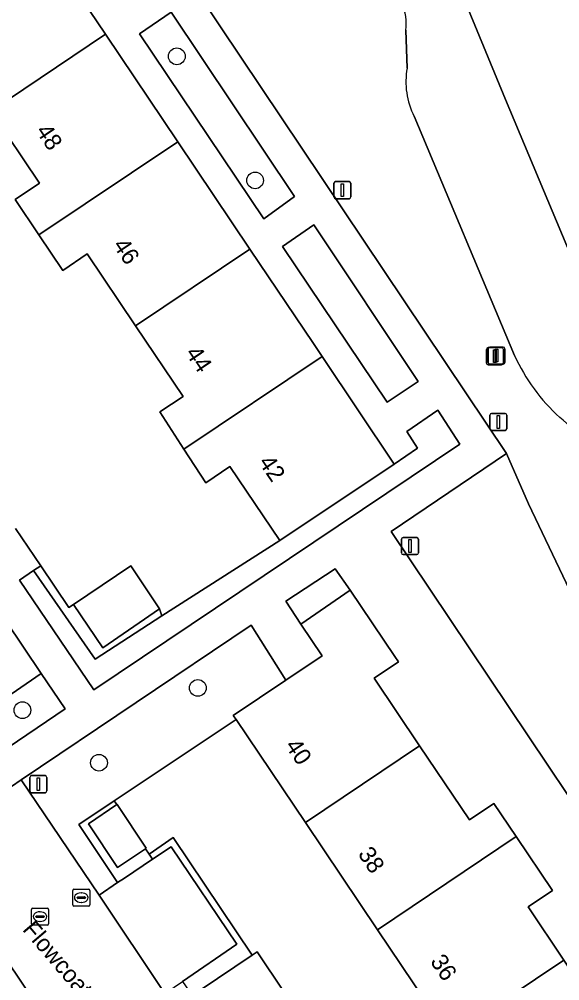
# Model space of a CAD drawing. Extents: x 158793 to 159888, y 384317 to 385256.
# Drawn here: x 159223.3 to 159254.9, y 384648 to 384704.4 of the extents above; entities that cross this region are included whole.
import ezdxf

# ---------------------------------------------------------------- set-up
doc = ezdxf.new("R2010")
doc.units = 0
for name, color, linetype in [('IMGEO_Berm_groen', 7, 'Continuous'), ('IMGEO_Boom', 7, 'Continuous'), ('IMGEO_Erf', 7, 'Continuous'), ('IMGEO_Groenvoorziening', 7, 'Continuous'), ('IMGEO_Kolk', 7, 'Continuous'), ('IMGEO_Lichtmast', 7, 'Continuous'), ('IMGEO_Openbare_ruimte_label', 7, 'Continuous'), ('IMGEO_Pand', 7, 'Continuous'), ('IMGEO_Pand_nummerreeks', 7, 'Continuous'), ('IMGEO_Parkeervlak_open', 7, 'Continuous'), ('IMGEO_Rijbaan_lokaal_gesloten', 7, 'Continuous'), ('IMGEO_Rijbaan_lokaal_open', 7, 'Continuous'), ('IMGEO_Rioolput', 7, 'Continuous'), ('IMGEO_Voetpad_open', 7, 'Continuous')]:
    doc.layers.add(name, color=color, linetype=linetype)

msp = doc.modelspace()

# ---------------------------------------------------------------- linework, layer by layer
at = {"layer": 'IMGEO_Berm_groen'}
msp.add_lwpolyline([(159216.952, 384783.693), (159217.253, 384782.828), (159218.327, 384780.517), (159221.58, 384772.678), (159236.092, 384737.711), (159251.77, 384699.675), (159258.087, 384684.588), (159260.49, 384679.327)], dxfattribs=at)
at = {"layer": 'IMGEO_Boom'}
for centre in [(159232.517, 384702.214), (159237.1, 384694.943), (159233.747, 384665.203), (159223.472, 384663.899), (159227.958, 384660.819)]:
    msp.add_circle(centre, 0.489, dxfattribs=at)
at = {"layer": 'IMGEO_Erf'}
for points in [[(159223.073, 384674.553), (159224.542, 384672.365), (159226.19, 384669.91), (159226.456, 384670.099), (159229.817, 384672.35), (159231.505, 384669.83), (159231.646, 384669.425), (159238.559, 384673.833), (159235.628, 384678.178), (159234.209, 384677.22), (159232.929, 384679.198), (159231.513, 384681.385), (159232.888, 384682.274), (159230.104, 384686.42), (159227.265, 384690.647), (159225.845, 384689.669), (159224.442, 384691.752), (159223.043, 384693.829), (159224.471, 384694.783), (159221.632, 384698.999)], [(159248.484, 384644.756), (159244.264, 384651.036), (159240.043, 384657.316), (159235.992, 384663.344), (159228.851, 384658.586), (159228.997, 384658.366), (159229.018, 384658.38), (159230.722, 384655.81), (159230.672, 384655.776), (159230.889, 384655.463), (159232.311, 384656.433), (159236.938, 384649.541), (159237.216, 384649.728), (159238.803, 384647.366)]]:
    msp.add_lwpolyline(points, dxfattribs=at)
at = {"layer": 'IMGEO_Groenvoorziening'}
for points in [[(159201.289, 384776.877), (159195.743, 384773.179), (159198.516, 384769.05), (159229.19, 384723.379), (159224.283, 384720.074), (159251.833, 384678.94), (159253.112, 384675.993), (159259.952, 384661.651), (159264.67, 384652.66), (159271.444, 384640.927), (159281.072, 384626.042), (159295.14, 384605.026), (159302.978, 384593.779), (159290.294, 384585.213), (159293.251, 384580.83)], [(159246.008, 384701.523), (159245.924, 384703.745)], [(159252.293, 384684.682), (159246.42, 384698.698)], [(159271.444, 384640.927), (159264.67, 384652.66), (159259.952, 384661.651), (159253.112, 384675.993), (159251.833, 384678.94), (159245.073, 384674.375), (159284.084, 384616.156)], [(159224.563, 384666.045), (159220.723, 384663.409)], [(159222.071, 384661.335), (159225.982, 384663.968), (159224.563, 384666.045)]]:
    msp.add_lwpolyline(points, dxfattribs=at)
for points in [[(159232.178, 384704.793), (159230.331, 384703.528), (159237.614, 384692.69), (159239.413, 384693.992)], [(159240.532, 384692.345), (159238.702, 384691.07), (159244.836, 384681.942), (159246.66, 384683.164)], [(159249.098, 384679.489), (159247.796, 384681.472), (159245.986, 384680.232), (159246.612, 384679.247), (159245.244, 384678.321), (159238.559, 384673.833), (159231.646, 384669.425), (159227.728, 384666.883), (159224.118, 384672.075), (159223.306, 384671.521), (159227.65, 384665.089)], [(159231.646, 384669.425), (159231.505, 384669.83), (159228.174, 384667.554), (159226.456, 384670.099), (159226.19, 384669.91), (159224.542, 384672.365), (159224.118, 384672.075), (159227.728, 384666.883)], [(159242.671, 384670.925), (159241.796, 384672.189), (159238.901, 384670.278), (159239.783, 384668.942)], [(159238.906, 384665.665), (159236.861, 384668.877), (159223.405, 384659.813), (159227.961, 384653.066), (159229.047, 384653.792), (159226.779, 384657.195), (159228.851, 384658.586), (159235.992, 384663.344), (159235.822, 384663.596)], [(159227.336, 384657.246), (159228.997, 384658.366), (159228.851, 384658.586), (159226.779, 384657.195), (159229.047, 384653.792), (159229.443, 384654.057), (159231.097, 384655.163), (159230.889, 384655.463), (159230.672, 384655.776), (159229.039, 384654.685)], [(159236.938, 384649.541), (159232.311, 384656.433), (159230.889, 384655.463), (159231.097, 384655.163), (159232.19, 384655.894), (159236.032, 384650.179), (159232.839, 384648.004), (159237.377, 384641.427), (159239.267, 384642.679), (159238.692, 384643.486), (159237.227, 384642.502), (159235.466, 384645.123), (159233.876, 384647.489)]]:
    msp.add_lwpolyline(points, close=True, dxfattribs=at)
for centre, radius, start, end in [((159242.978, 384704.132), 2.971, 352.5249, 23.1992), ((159250.334, 384700.711), 4.402, 169.374, 207.2212), ((159262.54, 384689.392), 11.277, 204.6838, 227.6579), ((159249.727, 384674.638), 8.271, 22.037, 50.8966)]:
    msp.add_arc(centre, radius, start, end, dxfattribs=at)
at = {"layer": 'IMGEO_Kolk'}
for p, q in [((159226.419, 384652.488), (159226.419, 384653.34)), ((159226.494, 384653.414), (159227.346, 384653.414)), ((159226.907, 384653.194), (159226.932, 384653.194)), ((159227.42, 384653.34), (159227.42, 384652.488)), ((159226.678, 384652.908), (159226.678, 384652.92)), ((159227.116, 384652.871), (159226.718, 384652.871)), ((159226.721, 384652.957), (159227.119, 384652.957)), ((159226.93, 384652.634), (159226.905, 384652.634)), ((159227.162, 384652.92), (159227.162, 384652.908)), ((159227.346, 384652.414), (159226.494, 384652.414))]:
    msp.add_line(p, q, dxfattribs=at)
for points in [[(159226.419, 384652.488), (159226.419, 384653.34)], [(159226.494, 384653.414), (159227.346, 384653.414)], [(159227.42, 384653.34), (159227.42, 384652.488)], [(159227.346, 384652.414), (159226.494, 384652.414)]]:
    msp.add_lwpolyline(points, dxfattribs=at)
for centre, radius, start, end in [((159226.496, 384653.338), 0.0765, 91.552, 178.448), ((159226.496, 384653.338), 0.0765, 91.552, 178.448), ((159227.344, 384653.338), 0.0765, 1.552, 88.448), ((159227.344, 384653.338), 0.0765, 1.552, 88.448), ((159226.718, 384652.917), 0.0403, 85.8775, 175.7526), ((159226.715, 384652.907), 0.0366, 178.938, 274.7102), ((159227.119, 384652.914), 0.043, 264.8664, 352.4533), ((159227.123, 384652.919), 0.0386, 1.7309, 96.639), ((159226.496, 384652.49), 0.0765, 181.552, 268.448), ((159226.496, 384652.49), 0.0765, 181.552, 268.448), ((159227.344, 384652.49), 0.0765, 271.552, 358.448), ((159227.344, 384652.49), 0.0765, 271.552, 358.448)]:
    msp.add_arc(centre, radius, start, end, dxfattribs=at)
for centre, major_axis, ratio, start_param, end_param in [((159226.906, 384652.914), (-0.387, 0.002), 0.722429, 4.712389, 7.853982), ((159226.931, 384652.914), (-0.39, 0.002), 0.717154, 1.570796, 4.712389)]:
    msp.add_ellipse(centre, major_axis=major_axis, ratio=ratio, start_param=start_param, end_param=end_param, dxfattribs=at)
at = {"layer": 'IMGEO_Lichtmast'}
for p, q in [((159241.815, 384694.873), (159242.605, 384694.873)), ((159242.605, 384694.873), (159241.815, 384694.873)), ((159241.715, 384693.973), (159241.715, 384694.773)), ((159241.715, 384694.773), (159241.715, 384693.973)), ((159242.705, 384694.773), (159242.705, 384693.973)), ((159242.705, 384693.973), (159242.705, 384694.773)), ((159242.605, 384693.873), (159241.815, 384693.873)), ((159241.815, 384693.873), (159242.605, 384693.873)), ((159250.65, 384684.242), (159250.65, 384685.042)), ((159250.65, 384685.042), (159250.65, 384684.242)), ((159250.745, 384684.279), (159250.745, 384685.079)), ((159250.745, 384685.079), (159250.745, 384684.279)), ((159250.75, 384685.142), (159251.54, 384685.142)), ((159251.54, 384685.142), (159250.75, 384685.142)), ((159250.845, 384685.179), (159251.635, 384685.179)), ((159251.635, 384685.179), (159250.845, 384685.179)), ((159251.64, 384685.042), (159251.64, 384684.242)), ((159251.64, 384684.242), (159251.64, 384685.042)), ((159251.735, 384685.079), (159251.735, 384684.279)), ((159251.735, 384684.279), (159251.735, 384685.079)), ((159251.54, 384684.142), (159250.75, 384684.142)), ((159250.75, 384684.142), (159251.54, 384684.142)), ((159251.635, 384684.179), (159250.845, 384684.179)), ((159250.845, 384684.179), (159251.635, 384684.179)), ((159250.952, 384681.288), (159251.742, 384681.288)), ((159251.742, 384681.288), (159250.952, 384681.288)), ((159250.852, 384680.388), (159250.852, 384681.188)), ((159250.852, 384681.188), (159250.852, 384680.388)), ((159251.842, 384681.188), (159251.842, 384680.388)), ((159251.842, 384680.388), (159251.842, 384681.188)), ((159251.742, 384680.288), (159250.952, 384680.288)), ((159250.952, 384680.288), (159251.742, 384680.288)), ((159245.775, 384674.016), (159246.565, 384674.016)), ((159246.565, 384674.016), (159245.775, 384674.016)), ((159245.675, 384673.116), (159245.675, 384673.916)), ((159245.675, 384673.916), (159245.675, 384673.116)), ((159246.665, 384673.916), (159246.665, 384673.116)), ((159246.665, 384673.116), (159246.665, 384673.916)), ((159246.565, 384673.016), (159245.775, 384673.016)), ((159245.775, 384673.016), (159246.565, 384673.016)), ((159223.913, 384659.163), (159223.913, 384659.963)), ((159223.913, 384659.963), (159223.913, 384659.163)), ((159224.013, 384660.063), (159224.803, 384660.063)), ((159224.803, 384660.063), (159224.013, 384660.063)), ((159224.903, 384659.963), (159224.903, 384659.163)), ((159224.903, 384659.163), (159224.903, 384659.963)), ((159224.803, 384659.063), (159224.013, 384659.063)), ((159224.013, 384659.063), (159224.803, 384659.063))]:
    msp.add_line(p, q, dxfattribs=at)
for points in [[(159242.135, 384694.748), (159242.285, 384694.748), (159242.285, 384693.998), (159242.135, 384693.998), (159242.135, 384694.748)], [(159251.07, 384685.017), (159251.22, 384685.017), (159251.22, 384684.267), (159251.07, 384684.267), (159251.07, 384685.017)], [(159251.165, 384685.054), (159251.315, 384685.054), (159251.315, 384684.304), (159251.165, 384684.304), (159251.165, 384685.054)], [(159251.272, 384681.163), (159251.422, 384681.163), (159251.422, 384680.413), (159251.272, 384680.413), (159251.272, 384681.163)], [(159246.095, 384673.891), (159246.245, 384673.891), (159246.245, 384673.141), (159246.095, 384673.141), (159246.095, 384673.891)], [(159224.333, 384659.938), (159224.483, 384659.938), (159224.483, 384659.188), (159224.333, 384659.188), (159224.333, 384659.938)]]:
    msp.add_lwpolyline(points, dxfattribs=at)
for centre, start, end in [((159241.815, 384694.773), 90, 180), ((159241.815, 384694.773), 90, 180), ((159242.605, 384694.773), 0, 90), ((159242.605, 384694.773), 360, 90), ((159241.815, 384693.973), 180, 270), ((159241.815, 384693.973), 180, 270), ((159242.605, 384693.973), 270, 0), ((159242.605, 384693.973), 270, 0), ((159250.75, 384685.042), 90, 180), ((159250.75, 384685.042), 90, 180), ((159250.845, 384685.079), 90, 180), ((159250.845, 384685.079), 90, 180), ((159251.54, 384685.042), 0, 90), ((159251.54, 384685.042), 360, 90), ((159251.635, 384685.079), 0, 90), ((159251.635, 384685.079), 360, 90), ((159250.75, 384684.242), 180, 270), ((159250.75, 384684.242), 180, 270), ((159250.845, 384684.279), 180, 270), ((159250.845, 384684.279), 180, 270), ((159251.54, 384684.242), 270, 0), ((159251.54, 384684.242), 270, 0), ((159251.635, 384684.279), 270, 0), ((159251.635, 384684.279), 270, 0), ((159250.952, 384681.188), 90, 180), ((159250.952, 384681.188), 90, 180), ((159251.742, 384681.188), 0, 90), ((159251.742, 384681.188), 360, 90), ((159250.952, 384680.388), 180, 270), ((159250.952, 384680.388), 180, 270), ((159251.742, 384680.388), 270, 0), ((159251.742, 384680.388), 270, 0), ((159245.775, 384673.916), 90, 180), ((159245.775, 384673.916), 90, 180), ((159246.565, 384673.916), 0, 90), ((159246.565, 384673.916), 360, 90), ((159245.775, 384673.116), 180, 270), ((159245.775, 384673.116), 180, 270), ((159246.565, 384673.116), 270, 0), ((159246.565, 384673.116), 270, 0), ((159224.013, 384659.963), 90, 180), ((159224.013, 384659.963), 90, 180), ((159224.803, 384659.963), 0, 90), ((159224.803, 384659.963), 360, 90), ((159224.013, 384659.163), 180, 270), ((159224.013, 384659.163), 180, 270), ((159224.803, 384659.163), 270, 0), ((159224.803, 384659.163), 270, 0)]:
    msp.add_arc(centre, 0.1, start, end, dxfattribs=at)
at = {"layer": 'IMGEO_Pand'}
for points in [[(159224.111, 384709.799), (159215.977, 384704.335), (159217.46, 384702.129), (159218.881, 384703.083), (159221.632, 384698.999), (159228.339, 384703.504)], [(159228.339, 384703.504), (159221.632, 384698.999), (159224.471, 384694.783), (159223.043, 384693.829), (159224.442, 384691.752), (159232.568, 384697.21)], [(159232.568, 384697.21), (159224.442, 384691.752), (159225.845, 384689.669), (159227.265, 384690.647), (159230.104, 384686.42), (159236.796, 384690.916)], [(159236.796, 384690.916), (159230.104, 384686.42), (159232.888, 384682.274), (159231.513, 384681.385), (159232.929, 384679.198), (159241.024, 384684.621), (159240.517, 384685.377)], [(159241.024, 384684.621), (159232.929, 384679.198), (159234.209, 384677.22), (159235.628, 384678.178), (159238.559, 384673.833), (159245.244, 384678.321)], [(159226.456, 384670.099), (159228.174, 384667.554), (159231.505, 384669.83), (159229.817, 384672.35)], [(159244.077, 384665.779), (159245.495, 384666.734), (159245.283, 384667.048), (159242.671, 384670.925), (159239.783, 384668.942), (159241.027, 384667.088), (159238.906, 384665.665), (159235.822, 384663.596), (159235.992, 384663.344), (159240.043, 384657.316), (159246.737, 384661.815)], [(159252.384, 384656.493), (159251.075, 384658.43), (159249.653, 384657.469), (159246.737, 384661.815), (159240.043, 384657.316), (159244.264, 384651.036)], [(159229.018, 384658.38), (159228.997, 384658.366), (159227.336, 384657.246), (159229.039, 384654.685), (159230.672, 384655.776), (159230.722, 384655.81)], [(159253.085, 384652.381), (159254.516, 384653.338), (159252.384, 384656.493), (159244.264, 384651.036), (159248.484, 384644.756), (159255.177, 384649.253)], [(159237.216, 384649.728), (159236.938, 384649.541), (159233.876, 384647.489), (159235.466, 384645.123), (159238.803, 384647.366)], [(159260.821, 384643.93), (159259.45, 384645.984), (159258.011, 384645.015), (159255.177, 384649.253), (159248.484, 384644.756), (159252.705, 384638.476)]]:
    msp.add_lwpolyline(points, close=True, dxfattribs=at)
at = {"layer": 'IMGEO_Parkeervlak_open'}
msp.add_lwpolyline([(159220.723, 384663.409), (159224.563, 384666.045), (159217.389, 384676.739)], dxfattribs=at)
msp.add_lwpolyline([(159231.097, 384655.163), (159229.443, 384654.057), (159229.047, 384653.792), (159227.961, 384653.066), (159231.807, 384647.301), (159232.839, 384648.004), (159236.032, 384650.179), (159232.19, 384655.894)], close=True, dxfattribs=at)
at = {"layer": 'IMGEO_Rijbaan_lokaal_gesloten'}
for points in [[(159260.49, 384679.327), (159258.087, 384684.588), (159251.77, 384699.675), (159236.092, 384737.711)], [(159245.924, 384703.745), (159246.008, 384701.523)], [(159246.42, 384698.698), (159252.293, 384684.682)]]:
    msp.add_lwpolyline(points, dxfattribs=at)
for centre, radius, start, end in [((159242.978, 384704.132), 2.971, 352.5249, 23.1992), ((159250.334, 384700.711), 4.402, 169.374, 207.2212), ((159262.54, 384689.392), 11.277, 204.6838, 227.6579), ((159249.727, 384674.638), 8.271, 22.037, 50.8966)]:
    msp.add_arc(centre, radius, start, end, dxfattribs=at)
at = {"layer": 'IMGEO_Rijbaan_lokaal_open'}
for points in [[(159188.783, 384699.493), (159214.301, 384661.55), (159213.504, 384661.015), (159214.075, 384660.15), (159216.618, 384656.317), (159217.267, 384655.359), (159218.072, 384655.9), (159243.588, 384617.955)], [(159231.807, 384647.301), (159227.961, 384653.066), (159223.405, 384659.813), (159222.843, 384659.434), (159221.515, 384661.409), (159221.497, 384661.435), (159220.56, 384662.818), (159212.912, 384674.206), (159212.099, 384675.434)]]:
    msp.add_lwpolyline(points, dxfattribs=at)
at = {"layer": 'IMGEO_Rioolput'}
for p, q in [((159224.002, 384651.376), (159224.002, 384652.228)), ((159224.077, 384652.302), (159224.929, 384652.302)), ((159224.49, 384652.082), (159224.515, 384652.082)), ((159225.003, 384652.228), (159225.003, 384651.376)), ((159224.261, 384651.796), (159224.261, 384651.808)), ((159224.699, 384651.759), (159224.301, 384651.759)), ((159224.304, 384651.845), (159224.702, 384651.845)), ((159224.513, 384651.522), (159224.488, 384651.522)), ((159224.745, 384651.808), (159224.745, 384651.796)), ((159224.929, 384651.302), (159224.077, 384651.302))]:
    msp.add_line(p, q, dxfattribs=at)
for points in [[(159224.002, 384651.376), (159224.002, 384652.228)], [(159224.077, 384652.302), (159224.929, 384652.302)], [(159225.003, 384652.228), (159225.003, 384651.376)], [(159224.929, 384651.302), (159224.077, 384651.302)]]:
    msp.add_lwpolyline(points, dxfattribs=at)
for centre, radius, start, end in [((159224.079, 384652.226), 0.0765, 91.552, 178.448), ((159224.079, 384652.226), 0.0765, 91.552, 178.448), ((159224.927, 384652.226), 0.0765, 1.552, 88.448), ((159224.927, 384652.226), 0.0765, 1.552, 88.448), ((159224.301, 384651.805), 0.0403, 85.8775, 175.7526), ((159224.298, 384651.795), 0.0366, 178.938, 274.7102), ((159224.702, 384651.802), 0.043, 264.8664, 352.4533), ((159224.706, 384651.807), 0.0386, 1.7309, 96.639), ((159224.079, 384651.378), 0.0765, 181.552, 268.448), ((159224.079, 384651.378), 0.0765, 181.552, 268.448), ((159224.927, 384651.378), 0.0765, 271.552, 358.448), ((159224.927, 384651.378), 0.0765, 271.552, 358.448)]:
    msp.add_arc(centre, radius, start, end, dxfattribs=at)
for centre, major_axis, ratio, start_param, end_param in [((159224.489, 384651.802), (-0.387, 0.002), 0.722429, 4.712389, 7.853982), ((159224.514, 384651.802), (-0.39, 0.002), 0.717154, 1.570796, 4.712389)]:
    msp.add_ellipse(centre, major_axis=major_axis, ratio=ratio, start_param=start_param, end_param=end_param, dxfattribs=at)
at = {"layer": 'IMGEO_Voetpad_open'}
for points in [[(159274.674, 384625.893), (159280.198, 384617.788), (159281.01, 384616.597), (159276.865, 384613.804), (159276.077, 384614.965), (159274.774, 384616.86), (159272.655, 384615.428), (159273.311, 384614.477), (159275.927, 384610.681), (159284.084, 384616.156), (159245.073, 384674.375), (159251.833, 384678.94), (159224.283, 384720.074)], [(159224.111, 384709.799), (159228.339, 384703.504), (159232.568, 384697.21), (159236.796, 384690.916), (159240.517, 384685.377), (159241.024, 384684.621), (159245.244, 384678.321), (159246.612, 384679.247), (159245.986, 384680.232), (159247.796, 384681.472), (159249.098, 384679.489), (159227.65, 384665.089), (159223.306, 384671.521), (159224.118, 384672.075), (159224.542, 384672.365), (159223.073, 384674.553)], [(159200.688, 384705.155), (159199.041, 384704.037), (159200.413, 384702.012), (159207.623, 384691.274), (159208.88, 384689.312), (159216.104, 384678.641), (159217.389, 384676.739), (159224.563, 384666.045), (159225.982, 384663.968), (159222.071, 384661.335)], [(159221.515, 384661.409), (159222.843, 384659.434), (159223.405, 384659.813), (159236.861, 384668.877), (159238.906, 384665.665), (159241.027, 384667.088), (159239.783, 384668.942), (159238.901, 384670.278), (159241.796, 384672.189), (159242.671, 384670.925), (159245.283, 384667.048), (159245.495, 384666.734), (159244.077, 384665.779), (159246.737, 384661.815), (159249.653, 384657.469), (159251.075, 384658.43), (159252.384, 384656.493), (159254.516, 384653.338), (159253.085, 384652.381), (159255.177, 384649.253), (159258.011, 384645.015)]]:
    msp.add_lwpolyline(points, dxfattribs=at)
for points in [[(159230.331, 384703.528), (159232.178, 384704.793), (159239.413, 384693.992), (159237.614, 384692.69)], [(159238.702, 384691.07), (159240.532, 384692.345), (159246.66, 384683.164), (159244.836, 384681.942)], [(159217.267, 384655.359), (159221.858, 384648.53), (159225.667, 384642.9), (159229.945, 384636.53), (159232.412, 384632.856), (159234.223, 384630.159), (159238.501, 384623.789), (159242.779, 384617.418), (159243.588, 384617.955), (159218.072, 384655.9)]]:
    msp.add_lwpolyline(points, close=True, dxfattribs=at)

# ---------------------------------------------------------------- texts
at = {"layer": 'IMGEO_Openbare_ruimte_label'}
msp.add_text('Flowcoatstraat', height=1, rotation=310.4956, dxfattribs=at).set_placement((159223.432, 384651.022))
at = {"layer": 'IMGEO_Pand_nummerreeks'}
for s, rotation, p in [('48', 303.959, (159224.222, 384697.839)), ('46', 303.8845, (159228.739, 384691.143)), ('44', 303.8845, (159232.986, 384684.818)), ('42', 304.0048, (159237.271, 384678.424)), ('40', 303.9017, (159238.824, 384661.818)), ('38', 303.9017, (159243.09, 384655.472)), ('36', 303.9017, (159247.324, 384649.172))]:
    msp.add_text(s, height=1, rotation=rotation, dxfattribs=at).set_placement(p)

doc.saveas('drawing.dxf')
